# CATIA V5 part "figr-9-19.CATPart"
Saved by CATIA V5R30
Part number: Part3
Bounding box of the stored display mesh (mm): x -17.259 to 115.9, y -137.259 to 0, z -17.083 to 17.083
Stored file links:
  D:\PROJECTS\CATIA V56R 2020\Resources\Parts File\c09_catia_v5_6r2020_prt\figr-9-19.CATPart
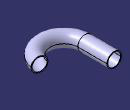
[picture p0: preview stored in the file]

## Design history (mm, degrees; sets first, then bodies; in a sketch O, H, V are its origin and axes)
Body1 (main body)
  Sketch1 on zx-plane, origin (0, 0, 0), H (-1, 0, 0), V (0, 0, 1)
    circle A1 centre (0, 0) radius 17.2586
  Sketch2 on xy-plane, origin (0, 0, 0), H (1, 0, 0), V (0, 1, 0)
    line L1 (0, 0) -> (0, -70)
    arc A1 centre (50, -70) radius 50 from (0, -70) to (50, -120) ccw
    arc A2 centre (50, -70) radius 50 from (50, -120) to (98.9898, -80) ccw
    vertical: L1 V
    tangency: A1 L1, A2 L1, A2 A1
  Rib1: profile Sketch1, centre curve Sketch2, thin wall 2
